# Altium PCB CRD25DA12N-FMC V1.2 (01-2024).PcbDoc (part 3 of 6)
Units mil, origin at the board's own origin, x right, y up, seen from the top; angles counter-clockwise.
Board outline 8000 x 8000 mil, 6 copper layers (Top Layer, Layer 2, Layer 3, Layer 4, Layer 5, Bottom Layer), stack 91 mil thick; 574 components, 325 nets, 1631 pads, 633 vias.
Unrouted connection lines stored in the file: 1.
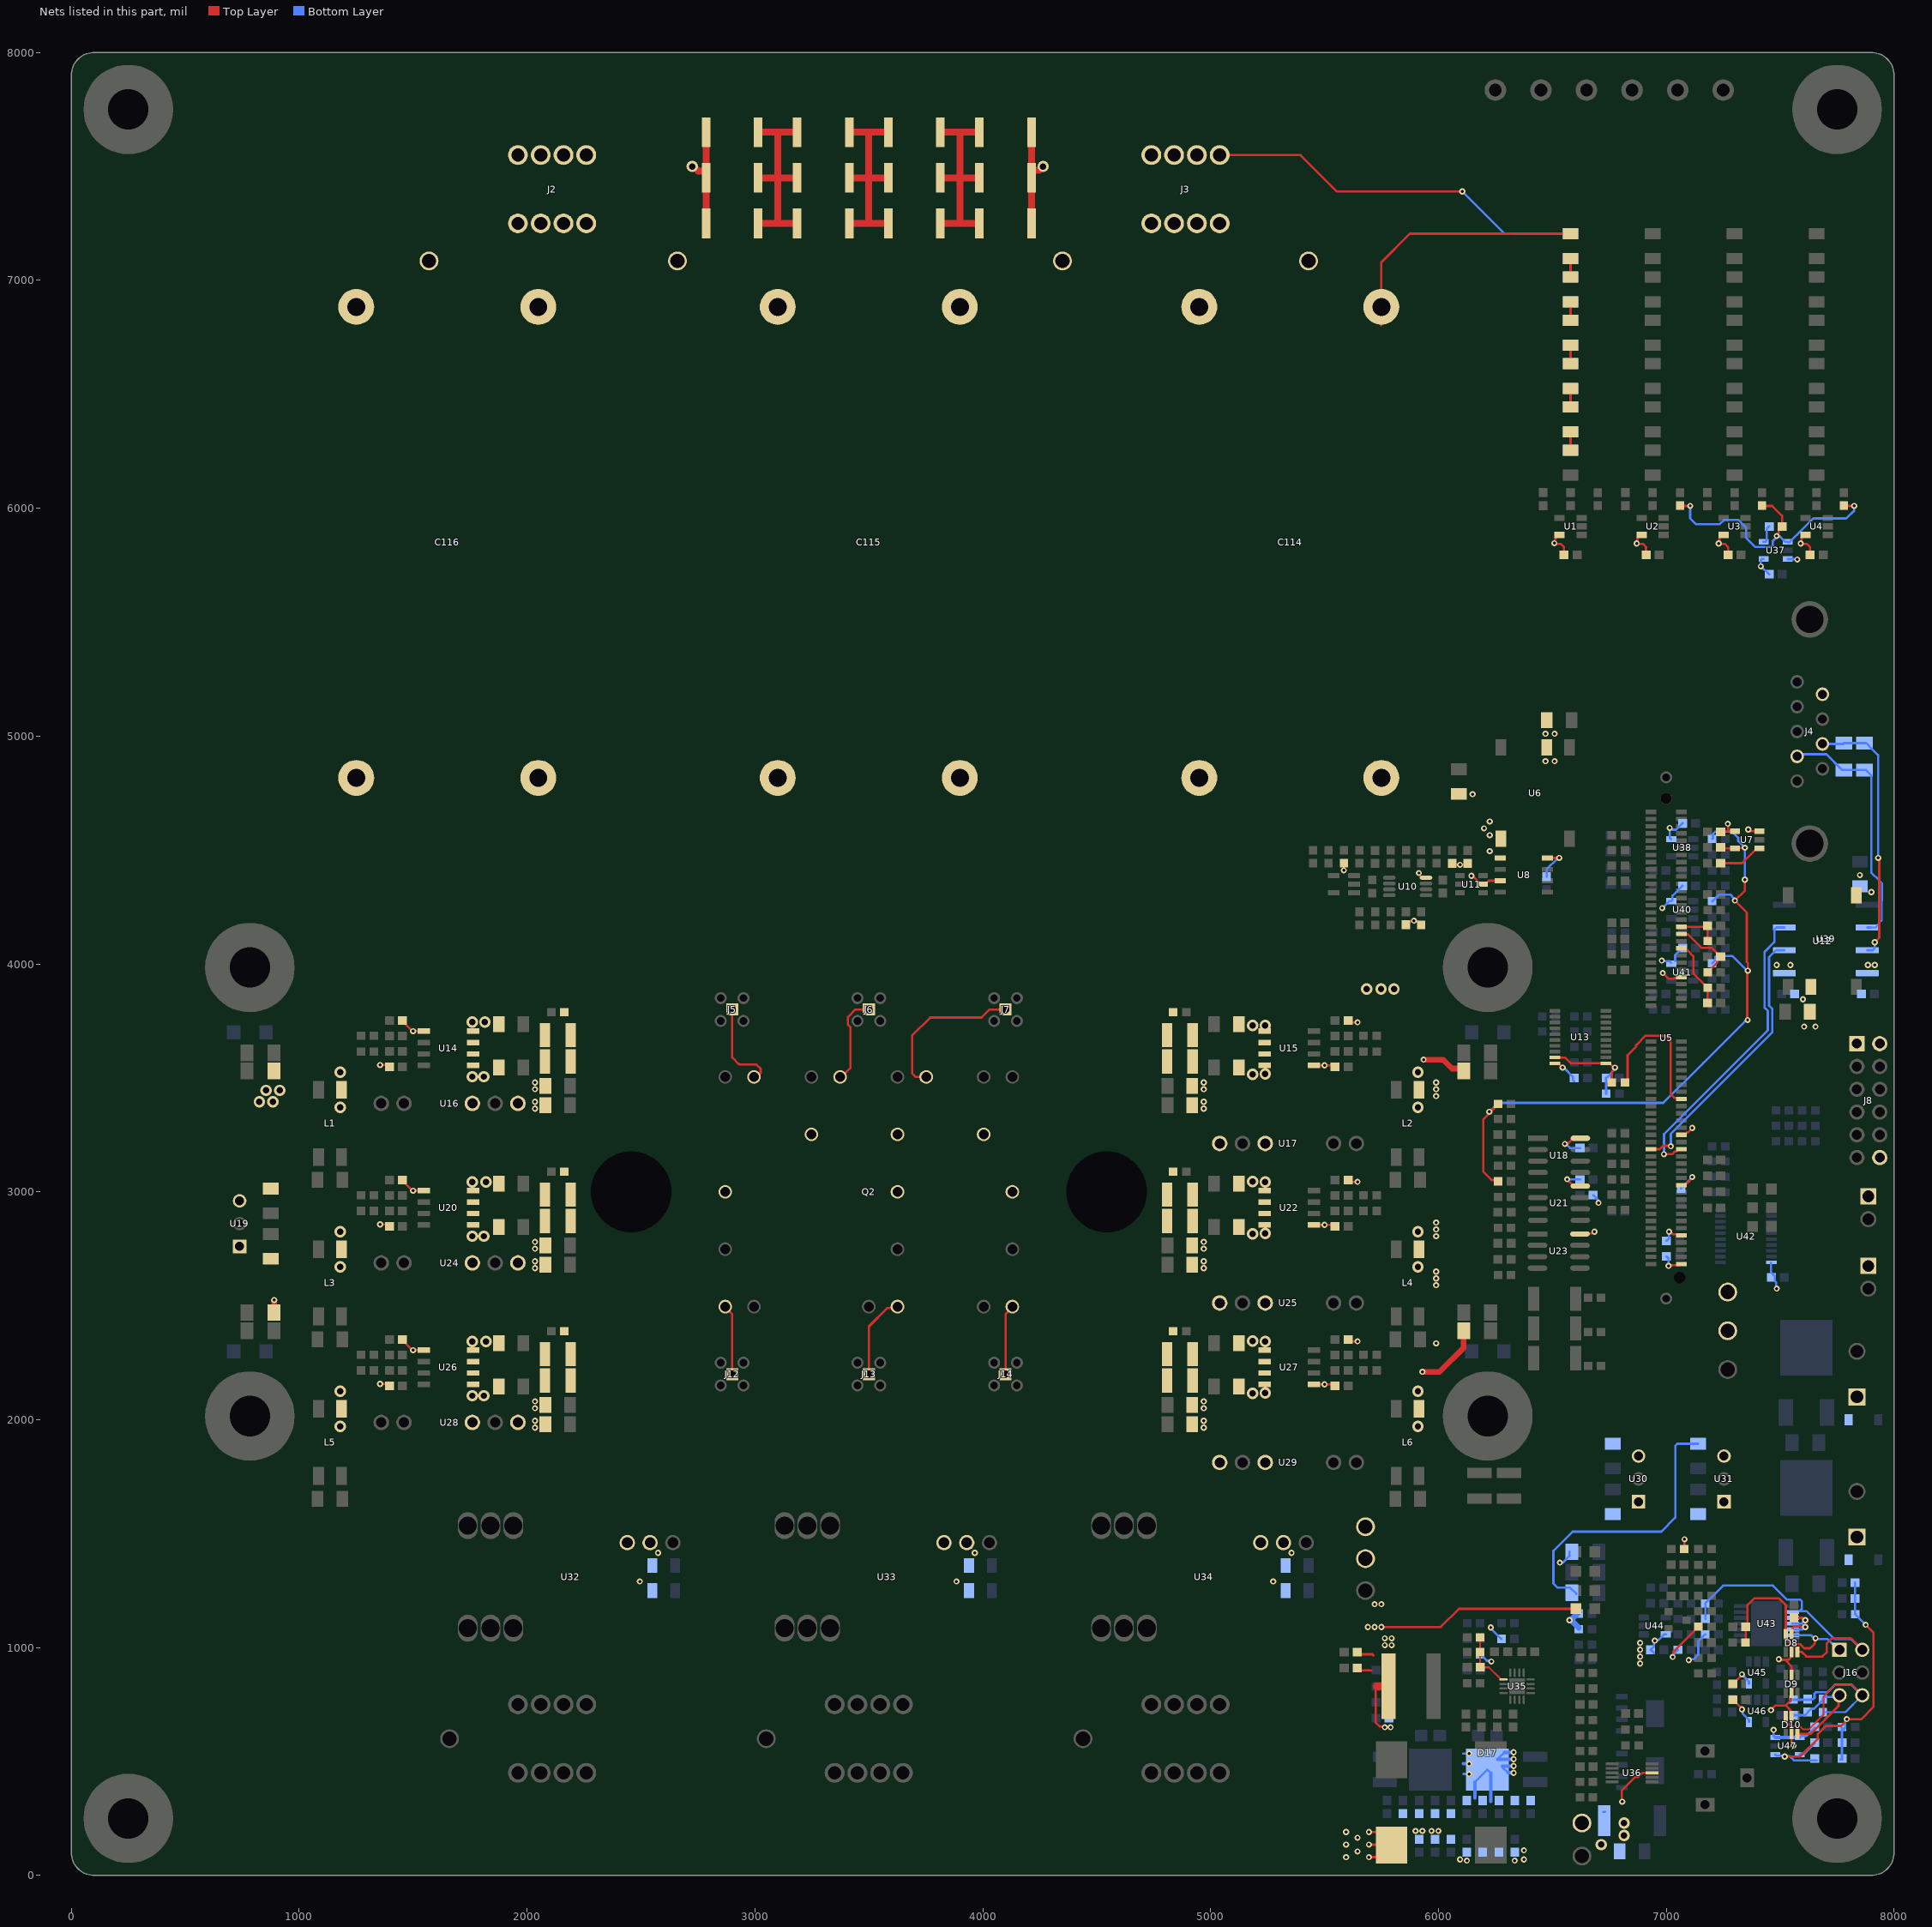
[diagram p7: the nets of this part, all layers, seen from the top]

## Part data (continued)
R51 R223 R227 R231 R234: "RES SMD 4.7K OHM 1% 1/10W 0603", Case Code (Imperial)=0603, Case Code (Metric)=1608, Manufacturer="VISHAY DALE", Max Operating Temperature=155°C, Max Power Dissipation=100mW, Min Operating Temperature=-55°C, Package Quantity=5000, Power Rating=0.1W, Resistance=4.7kΩ, Resistor Type="Thick Film", Supplier Part Number 1=541-3004-6-ND, Temperature Coefficient=100ppm/°C, Tolerance=1%, Voltage Rating=75V
R53: "RES SMD 0 OHM JUMPER 1/10W 0603", Case Code (Imperial)=0603, Case Code (Metric)=1608, Manufacturer="VISHAY DALE", Manufacturer Part Number=CRCW06030000Z0EBC, Max Operating Temperature=155°C, Max Power Dissipation=100mW, Min Operating Temperature=-55°C, Package Quantity=10000, Power Rating=0.1W, Ratings=AEC-Q200, Resistance=0Ω, Resistor Type="Thick Film", Supplier Part Number 1=48P7902, Temperature Coefficient=100ppm/°C, Tolerance=1%, Voltage Rating=75V
R56 R204 R205 R206 R207 R208 R209: "RES 330 OHM 1% 1/10W 0603", Case Code (Imperial)=0603, Case Code (Metric)=1608, Manufacturer=YAGEO, Max Operating Temperature=155°C, Min Operating Temperature=-55°C, Power Rating=0.1W, Resistance=330Ω, Resistor Type="Thick Film", Supplier Part Number 1=4067719, Temperature Coefficient=100ppm/°C, Tolerance=1%, Voltage Rating=50V
R58 R63 R106 R114 R120 R143 R226: "RES SMD 2K OHM 0.5% 1/10W 0603", Case Code (Imperial)=0603, Case Code (Metric)=1608, Manufacturer=YAGEO, Max Operating Temperature=125°C, Max Power Dissipation=100mW, Min Operating Temperature=-55°C, Package Quantity=5000, Power Rating=0.1W, Resistance=2kΩ, Resistor Type="Thin Film", Supplier Part Number 1=6165116, Temperature Coefficient=50ppm/°C, Tolerance=0.5%, Voltage Rating=75V, Voltage Rating (DC)=50V
R60: "RES 249K OHM 1% 1/10W 0603", Case Code (Imperial)=0603, Case Code (Metric)=1608, Manufacturer=STACKPOLE, Max Operating Temperature=155°C, Max Power Dissipation=0.1W, Min Operating Temperature=-55°C, Resistance=249kΩ, Resistor Type="Thick Film", Temperature Coefficient=100ppm/°C, Tolerance=1%
R62: "RES SMD 97.6K OHM 1% 1/10W 0603", Case Code (Imperial)=0603, Case Code (Metric)=1608, Manufacturer=PANASONIC, Max Operating Temperature=155°C, Max Power Dissipation=0.1W, Min Operating Temperature=-55°C, Package Quantity=1, Power Rating=100mW, Resistance=97.6kΩ, Resistance Tolerance=1%, Resistor Type="Thick Film", Supplier Part Number 1=27AC5274, Temperature Coefficient=100ppm/°C, Voltage Rating=75V, Voltage Rating (DC)=50V
R65 R66 R210 R211 R212 R213: "RES SMD 0 OHM JUMPER 1/10W 0603", Case Code (Imperial)=0603, Case Code (Metric)=1608, Manufacturer="VISHAY DALE", Manufacturer Part Number=CRCW06030000Z0EBC, Max Operating Temperature=155°C, Max Power Dissipation=100mW, Min Operating Temperature=-55°C, Package Quantity=10000, Ratings=AEC-Q200, Resistance=0Ω, Resistor Type="Thick Film", Supplier Part Number 1=48P7902, Temperature Coefficient=100ppm/°C, Tolerance=1%, Voltage Rating=75V
R69 R78 R92 R102 R115 R124 R125 R126: "RES SMD 0 OHM JUMPER 3/4W 1210", Case Code (Imperial)=1210, Case Code (Metric)=3225, Manufacturer="VISHAY DALE", Max Operating Temperature=155°C, Max Power Dissipation=750mW, Min Operating Temperature=-55°C, Package Quantity=10, Power Rating=0.75W, Resistance=0Ω, Supplier Part Number 1=71-CRCW12100000Z0EAH
R70 R77 R93 R101 R116 R123: library part CMP-2005-02198-1, "RES 0.91 OHM 1% 1W 1210", Manufacturer="VISHAY DALE", Package=1210, Power=1W
R73 R74 R79 R80 R107 R108 R110 R111 R181 R182 R214 R215 R216 R217 R219: "RES 249 OHM 1% 1/4W 1206", Case Code (Imperial)=1206, Case Code (Metric)=3216, Manufacturer=YAGEO, Max Operating Temperature=155°C, Max Power Dissipation=250mW, Min Operating Temperature=-55°C, Power Rating=0.25W, Resistance=249Ω, Resistor Type="Thick Film", Supplier Part Number 1=1142064, Temperature Coefficient=100ppm/°C, Tolerance=1%, Voltage Rating=200V
R105 R109 R117: library part CMP-1017-00397-1, "RES 100 OHM 1% 3/4W 2010", Case-Metric=5025, Manufacturer=YAGEO, Package=2010, Power="0.75 W", Tolerance="1 %"
R129 R138 R142 R144 R146 R197 R198 R199 R200 R201 R202 R246: "RES 100K OHM 1% 1/10W 0603", Case Code (Imperial)=0603, Case Code (Metric)=1608, Manufacturer=YAGEO, Max Operating Temperature=155°C, Max Power Dissipation=100mW, Min Operating Temperature=-55°C, Power Rating=0.1W, Resistance=100kΩ, Resistance Tolerance=1%, Resistor Type="Thick Film", Supplier Part Number 1=3697448, Temperature Coefficient=100ppm/°C, Voltage Rating=50V, Working Voltage=75V
R132: "RES 20 OHM 5% 1/10W 0603", Case Code (Imperial)=0603, Case Code (Metric)=1608, Manufacturer=YAGEO, Max Operating Temperature=155°C, Max Power Dissipation=100mW, Min Operating Temperature=-55°C, Package Quantity=1, Power Rating=0.1W, Resistance=20Ω, Resistance Tolerance=5%, Resistor Type="Thick Film", Supplier Part Number 1=4144481, Temperature Coefficient=100ppm/°C, Voltage Rating=75V, Voltage Rating (DC)=50V
R134: "RES 5.49K OHM 1% 1/10W 0603", Case Code (Imperial)=0603, Case Code (Metric)=1608, Manufacturer=YAGEO, Max Operating Temperature=155°C, Max Power Dissipation=100mW, Min Operating Temperature=-55°C, Package Quantity=5000, Power Rating=0.1W, Resistance=5.49kΩ, Supplier Part Number 1=1172345, Temperature Coefficient=100ppm/°C, Tolerance=1%, Voltage Rating=50V
R135 R220: "RES 470K OHM 1% 1/10W 0603", Case Code (Imperial)=0603, Case Code (Metric)=1608, Manufacturer=YAGEO, Max Operating Temperature=155°C, Max Power Dissipation=100mW, Min Operating Temperature=-55°C, Package Quantity=1, Power Rating=0.1W, Resistance=470kΩ, Resistance Tolerance=1%, Resistor Type="Thick Film", Supplier Part Number 1=4599155, Temperature Coefficient=100ppm/°C, Voltage Rating=50V
R136: "RES SMD 71.5KOHM 0.5% 1/10W 0603", Case Code (Imperial)=0603, Case Code (Metric)=1608, Manufacturer=YAGEO, Max Operating Temperature=155°C, Max Power Dissipation=0.1W, Min Operating Temperature=-55°C, Package Quantity=5000, Resistance=71.5kΩ, Supplier Part Number 1=3077636, Temperature Coefficient=50ppm/°C, Tolerance=0.5%, Voltage Rating (DC)=50V
R137: "RES SMD 49.9K OHM 1% 1/10W 0603", Case Code (Imperial)=0603, Case Code (Metric)=1608, Manufacturer=YAGEO, Max Operating Temperature=125°C, Max Power Dissipation=100mW, Min Operating Temperature=-55°C, Power Rating=0.1W, Resistance=49.9kΩ, Supplier Part Number 1=3100550, Temperature Coefficient=50ppm/°C, Tolerance=1%, Voltage Rating=75V, Voltage Rating (DC)=50V
R139: "RES 24.9K OHM 1% 1/10W 0603", Case Code (Imperial)=0603, Case Code (Metric)=1608, Manufacturer=YAGEO, Max Operating Temperature=155°C, Max Power Dissipation=100mW, Min Operating Temperature=-55°C, Package Quantity=1, Power Rating=0.1W, Resistance=24.9kΩ, Supplier Part Number 1=3435880, Temperature Coefficient=100ppm/°C, Tolerance=1%, Voltage Rating=50V
R141: "RES 61.9K OHM 1% 1/10W 0603", Case Code (Imperial)=0603, Case Code (Metric)=1608, Manufacturer=YAGEO, Max Operating Temperature=155°C, Max Power Dissipation=100mW, Min Operating Temperature=-55°C, Package Quantity=5000, Power Rating=0.1W, Resistance=61.9kΩ, Supplier Part Number 1=9857970, Temperature Coefficient=100ppm/°C, Tolerance=1%, Voltage Rating=50V, Working Voltage=75V
R147 R148: "RES 2.7M OHM 5% 1/10W 0603", Case Code (Imperial)=0603, Case Code (Metric)=1608, Manufacturer=YAGEO, Max Operating Temperature=155°C, Max Power Dissipation=100mW, Min Operating Temperature=-55°C, Package Quantity=1, Power Rating=0.1W, Resistance=2.7MΩ, Resistor Type="Thick Film", Temperature Coefficient=100ppm/°C, Tolerance=5%, Voltage Rating=75V, Voltage Rating (DC)=50V
R183 R187 R193: "RES 1.33K OHM 1% 1/10W 0603", Case Code (Imperial)=0603, Case Code (Metric)=1608, Manufacturer=STACKPOLE, Max Operating Temperature=155°C, Max Power Dissipation=100mW, Min Operating Temperature=-55°C, Power Rating=0.1W, Resistance=1.33kΩ, Resistor Type="Thick Film", Temperature Coefficient=100ppm/°C, Tolerance=1%
R184 R188 R194: "RES 7.15K OHM 1% 1/10W 0603", Case Code (Imperial)=0603, Case Code (Metric)=1608, Manufacturer=STACKPOLE, Max Operating Temperature=155°C, Max Power Dissipation=100mW, Min Operating Temperature=-55°C, Power Rating=0.1W, Resistance=7.15kΩ, Resistor Type="Thick Film", Temperature Coefficient=100ppm/°C, Tolerance=1%
R185 R190 R195: "RES SMD 4.02KOHM 0.1% 1/10W 0603", Case Code (Imperial)=0603, Case Code (Metric)=1608, Manufacturer=PANASONIC, Manufacturer Part Number=ERA-3AEB4021V, Max Operating Temperature=155°C, Max Power Dissipation=100mW, Min Operating Temperature=-55°C, Package Quantity=1, Power Rating=0.1W, Resistance=4.02kΩ, Resistance Tolerance=0.1%, Resistor Type="Thin Film", Supplier Part Number 1=7087616, Temperature Coefficient=25ppm/°C, Voltage Rating=75V
R186 R191 R196: "RES 7.87K OHM 1% 1/10W 0603", Case Code (Imperial)=0603, Case Code (Metric)=1608, Manufacturer=YAGEO, Max Operating Temperature=155°C, Max Power Dissipation=0.1W, Min Operating Temperature=-55°C, Package Quantity=1, Power Rating=100mW, Resistance=7.87kΩ, Resistor Type="Thick Film", Supplier Part Number 1=49AK2736, Temperature Coefficient=100ppm/°C, Tolerance=1%, Voltage Rating=50V
R218 R224: "RES SMD 3.9K OHM 1% 1/10W 0603", Case Code (Imperial)=0603, Case Code (Metric)=1608, Manufacturer=PANASONIC, Manufacturer Part Number=ERJ-3EKF3901V, Max Operating Temperature=155°C, Max Power Dissipation=100mW, Min Operating Temperature=-55°C, Package Quantity=1, Power Rating=0.1W, Resistance=3.9kΩ, Resistance Tolerance=1%, Resistor Type="Thick Film", Supplier Part Number 1=1229307, Temperature Coefficient=100ppm/°C, Voltage Rating=75V
R221 R228: "RES SMD 15K OHM 0.5% 1/10W 0603", Case Code (Imperial)=0603, Case Code (Metric)=1608, Manufacturer=PANASONIC, Max Operating Temperature=155°C, Max Power Dissipation=100mW, Min Operating Temperature=-55°C, Package Quantity=5000, Power Rating=0.1W, Ratings=AEC-Q200, Resistance=15kΩ, Resistance Tolerance=0.5%, Resistor Type="Thin Film", Supplier Part Number 1=P15KBLCT-ND, Temperature Coefficient=25ppm/°C, Voltage Rating=75V
R225: "RES SMD 34.8KOHM 0.5% 1/10W 0603", Case Code (Imperial)=0603, Case Code (Metric)=1608, Manufacturer=YAGEO, Max Operating Temperature=155°C, Max Power Dissipation=100mW, Min Operating Temperature=-55°C, Package Quantity=5000, Power Rating=0.1W, Resistance=34.8kΩ, Supplier Part Number 1=311-2545-1-ND, Temperature Coefficient=50ppm/°C, Tolerance=0.5%, Voltage Rating=75V, Voltage Rating (DC)=50V
R230: "RES SMD 22.6KOHM 0.5% 1/10W 0603", Case Code (Imperial)=0603, Case Code (Metric)=1608, Manufacturer=YAGEO, Max Operating Temperature=155°C, Max Power Dissipation=0.1W, Min Operating Temperature=-55°C, Package Quantity=5000, Resistance=22.6kΩ, Supplier Part Number 1=311-2487-1-ND, Temperature Coefficient=50ppm/°C, Tolerance=0.5%, Voltage Rating (DC)=50V
R233: "RES SMD 5.36KOHM 0.1% 1/10W 0603", Case Code (Imperial)=0603, Case Code (Metric)=1608, Manufacturer=YAGEO, Max Operating Temperature=155°C, Max Power Dissipation=100mW, Min Operating Temperature=-55°C, Package Quantity=5000, Power Rating=0.1W, Resistance=5.36kΩ, Supplier Part Number 1=YAG1697CT-ND, Temperature Coefficient=25ppm/°C, Tolerance=0.1%, Voltage Rating=75V, Voltage Rating (DC)=50V
R235 R238 R240 R242: "RES SMD 12.1K OHM 0.1% 1/5W 0603", Case Code (Imperial)=0603, Case Code (Metric)=1608, Manufacturer=PANASONIC, Max Operating Temperature=155°C, Max Power Dissipation=0.2W, Min Operating Temperature=-55°C, Resistance=12.1kΩ, Resistor Type="Thick Film", Supplier Part Number 1=68AC5970, Temperature Coefficient=50ppm/°C, Tolerance=0.1%
R236 R239: "RES 47K OHM 1% 1/10W 0603", Case Code (Imperial)=0603, Case Code (Metric)=1608, Manufacturer=YAGEO, Max Operating Temperature=155°C, Max Power Dissipation=100mW, Min Operating Temperature=-55°C, Package Quantity=1, Power Rating=0.1W, Resistance=47kΩ, Resistance Tolerance=1%, Resistor Type="Thick Film", Supplier Part Number 1=6616189, Temperature Coefficient=100ppm/°C, Voltage Rating=50V
R244 R245: "RES SMD 10 OHM 1% 3/4W 1210", Case Code (Imperial)=1210, Case Code (Metric)=3225, Manufacturer=VISHAY, Max Operating Temperature=155°C, Max Power Dissipation=750mW, Min Operating Temperature=-55°C, Package Quantity=10, Power Rating=0.75W, Ratings=AEC-Q200, Resistance=10Ω, Supplier Part Number 1=71-CRCW121010R0FKEAH, Temperature Coefficient=100ppm/°C, Tolerance=1%, Voltage Rating=200V
R247: "RES 0.01 OHM 1% 2W 2512", Case Code (Imperial)=2512, Case Code (Metric)=6432, Manufacturer=YAGEO, Max Operating Temperature=170°C, Max Power Dissipation=2W, Min Operating Temperature=-55°C, Resistance=10mΩ, Resistor Type="Metal Film", Supplier Part Number 1=1995902P, Temperature Coefficient=50ppm/°C, Tolerance=1%
TP1 TP2 TP5 TP6 TP8 TP9 TP14: library part CMP-1672-00002-4, "PC TEST POINT MULTIPURPOSE RED", Colour=Red, Manufacturer=KEYSTONE, Package=N/A, Package Quantity=100
TP3 TP4 TP7 TP10 TP15: library part CMP-1672-00003-4, "PC TEST POINT MULTIPURPOSE BLACK", Colour=Black, Manufacturer=KEYSTONE, Package=N/A, Package Quantity=100
TP11 TP12 TP13: library part CMP-1672-00004-4, "PC TEST POINT MULTIPURPOSE WHITE", Colour=White, Manufacturer=KEYSTONE, Package=N/A, Package Quantity=100
U1 U2 U3 U4 U38 U40 U41 U44 U45 U46: library part CMP-0384-02059-2, "IC OPAMP GP 1 CIRCUIT TSOT23-5", Amplifiers Per Package=1, Generic Part Number=AD8615, Input Bias Current=200fA, Input Offset Voltage=80uV, Manufacturer="ANALOG DEVICES", Package=TSOT-23-5
U5: "EVAL BOARD FOR TMS320F280039C", Manufacturer="TEXAS INSTRUMENTS", Package=N/A, Supplier Part Number 1=595-TMDSCNCD280039C
U6 U12: "DC DC CONVERTER 5V 1W", Case/Package=SMD/SMT, Current - Output 1=200mA, Isolation Voltage=2kV, Manufacturer=RECOM, Max Input Voltage=3.63V, Max Operating Temperature=100°C, Max Output Power=1W, Max Output Voltage=5V, Min Input Voltage=2.97V, Min Operating Temperature=-40°C, Package=8-SMD, Supplier Part Number 1=945-R1SE-3.305/H2-RCT-ND
U7 U37 U47: "AUTOMOTIVE LOW-DRIFT, LOW-POWER,", Manufacturer="TEXAS INSTRUMENTS", Package=TSOT-23-5, Supplier Part Number 1=595-REF2033QDDCRQ1
U8: library part CMP-0328-00055-4, "DGTL ISO 2500VRMS 1CH GP 8SOIC", Case/Package=8-SOIC, Insulation Rating(VRMS)=2500, Manufacturer="TEXAS INSTRUMENTS", Rating=Catalog, Supply Voltage(s)(V)="3.3, 5"
U9: "IC VREF SHUNT ADJ 2% SOT23-5", Case/Package=SOT-23-5, Cathode Current=60uA, Manufacturer=STMICROELECTRONICS, Manufacturer Print=ST, Max Input Voltage=10V, Max Operating Temperature=125°C, Max Output Current=30mA, Max Output Voltage=6V, Min Operating Temperature=-40°C, Min Output Voltage=1.24V, Package Quantity=1, Temperature Coefficient=100ppm/°C, Tolerance=2%
U10: "IC OPAMP GP 2 CIRCUIT 8MSOP", Case/Package=MSOP, Input Bias Current=1pA, Input Offset Voltage (Vos)=3mV, Input Offset Voltage-Max=5mV, Manufacturer=MICROCHIP, Max Operating Temperature=125°C, Max Supply Voltage=5.5V, Min Operating Temperature=-40°C, Min Supply Voltage=2.4V, Nominal Supply Current=1mA, Output Current=25mA, Package=8-MSOP, Package Quantity=100, Power Supply Rejection Ratio (PSRR)=70dB, Supplier Part Number 1=20T6022, Voltage Gain=110dB
U11: "IC OSC SILICON PROG TSOT23-6", Frequency=3.81Hz, Manufacturer="ANALOG DEVICES", Max Operating Temperature=70°C, Max Supply Voltage=5.5V, Min Operating Temperature=0°C, Min Supply Voltage=2.25V, Operating Supply Current=365uA, Package=TSOT-23-6, Package Quantity=1, Supplier Part Number 1=505-LTC6992CS6-2#TRMPBFDKR-ND
U13 U42: library part CMP-0440-01163-3, "IC BUF NON-INVERT 5.5V 20TSSOP", F @ Nom Voltage(Max)(Mhz)=110, Generic Part Number=SN74LV541AT, ICC @ Nom Voltage(Max)(mA)=0.02, Manufacturer="TEXAS INSTRUMENTS", Operating Temperature Range(C)="-40 to 125", Package=20-TSSOP, Rating=Catalog, tpd @ Nom Voltage(Max)(ns)=7.9, Voltage(Nom)(V)=5
U14 U15 U20 U22 U26 U27: "5A/5A, 3-KVRMS SINGLE-CHANNEL IS", Manufacturer="TEXAS INSTRUMENTS", Max Operating Temperature=125°C, Mfr_Name="Texas Instruments", Min Operating Temperature=-40°C, Package=8-SOIC, Supplier Part Number 1=296-47508-ND, Working Voltage=990V
U16 U17 U24 U25 U28 U29: "DC DC CONVERTER 15V -3V 1.7W", Manufacturer=MURATA, Package=7-SIP, Supplier Part Number 1=580-MGJ2D121503SC
U18 U21 U23: library part CMP-04896-000023-1, "IC COMPARATOR R-R HI-SPD 8-SOIC", Ambient Temperature Range High=+125°C, Ambient Temperature Range Low=-40°C, Input Bias Current=0.000002uA, Input Offset Voltage=1mV, Manufacturer="TEXAS INSTRUMENTS", Max Junction Temp=+150°C, Max Supply Voltage=5.5V, Min Supply Voltage=2.2V, Nominal Supply Current=3.2mA, Package=8-SOIC, Temperature="-40°C to +125°C"
U19 U31: "DC DC CONVERTER 5V 5W", Case/Package=SIP, Current - Output 1=1A, Manufacturer=RECOM, Max Input Voltage=28V, Max Operating Temperature=85°C, Max Output Voltage=5V, Max Power Dissipation=5W, Min Input Voltage=8V, Min Operating Temperature=-40°C, Package=3-SIP, Package Quantity=42, Supplier Part Number 1=1446013
U30: "DC DC CONVERTER 3.3V 3W", Case/Package=SIP, Manufacturer=RECOM, Max Input Voltage=28V, Max Operating Temperature=85°C, Max Output Current=1A, Max Output Power=3.3W, Max Output Voltage=3.3V, Max Power Dissipation=3W, Min Input Voltage=8V, Min Input Voltage (DC)=7V, Min Operating Temperature=-40°C, Package=3-SIP, Supplier Part Number 1=9176626
U32 U33 U34: "SENSOR CURRENT HALL 50A AC/DC", Case/Package=Module, Current Rating=50A, Frequency=200kHz, Manufacturer=LEM, Max Operating Temperature=85°C, Max Supply Current=35mA, Min Operating Temperature=-25°C, Operating Supply Voltage=15V, Package=N/A, Package Quantity=12, Secondary Current=25mA, Supplier Part Number 1=44W8442
U35: "IC REG MULT CONFG ADJ 6.5A 16QFN", Case/Package=16-WFQFN, Manufacturer="TEXAS INSTRUMENTS", Supplier Part Number 1=595-LM5157QRTERQ1
U36: "IC SURGE SUPPRESSION ADJ 10MSOP", Manufacturer="ANALOG DEVICES", Package=10-MSOP, Supplier Part Number 1=505-LTC4368IMS-2#PBF-ND
U39: "IC TXRX/ISO HALF 1/1 8SOP", Drivers Per Package=1, Manufacturer="TEXAS INSTRUMENTS", Package=8-SOP, Rating=Catalog
U43: library part CMP-04895-000282-1, "IC POWER 2 CIRCUIT 14HTSSOP", Manufacturer="TEXAS INSTRUMENTS", Package=14-PowerTSSOP

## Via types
v1: diameter 27, hole 13, Top Layer to Bottom Layer, tented both sides, 537 vias
v2: diameter 50, hole 28, Top Layer to Bottom Layer, tented both sides, 76 vias
v3: diameter 19.68, hole 7.87, Top Layer to Bottom Layer, tented top, 15 vias
v4: diameter 19.68, hole 7.87, Top Layer to Bottom Layer, tented both sides, 5 vias

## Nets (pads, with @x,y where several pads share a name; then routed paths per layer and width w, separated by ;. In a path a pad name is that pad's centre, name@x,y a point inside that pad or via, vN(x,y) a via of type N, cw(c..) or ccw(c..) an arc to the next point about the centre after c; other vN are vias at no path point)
+1.65V_I: C17.1 U7.1 | length 196.7
  Top Layer w10: C17.1@7238.58,4442 7332.71,4442 7398.31,4507.6 U7.1@7408.15,4507.6
+1.65V_R: C165.1 C169.1 C185.1 C187.1 C188.1 R222.1 R243.1 U47.1 | length 1476.3
  Top Layer w10: v1(7520,521.49) 7586.8,521.49 7665,599.69 7665,620.31 7700.64,655.94 7767.72,655.94 7775.01,663.23 7775.01,663.81 7792.41,681.2 v1(7792.41,685.8) 7793.21,685 7820.91,685 7855,685 7910,740 7910,1065 v1(7875,1100)
  Bottom Layer w10: U47.1@7478.7,530.2 7484.15,524.74 7516.75,524.74 v1(7520,521.49) 7521.6,523.09 7541.91,523.09 7560,505 C188.1@7660.37,505 ; C187.1@7765.47,508 7771.42,508 C187.1@7771.42,513 7771.42,577.05 7770.47,578 7771.42,578 C185.1@7771.42,583 7771.42,634 ; R243.1@7771.38,647 7771.42,646.96 7771.42,634 ; v1(7792.41,685.8) 7792.41,681.2 7785.24,674.03 7785.24,646.96 7772.28,634 7771.42,634 ; C165.1@7828.58,1285 C169.1@7828.58,1215 C169.1@7828.58,1215 R222.1@7828.62,1146 7829.53,1146 7875,1100.53 v1(7875,1100)
+1.65V_V: C5.1 R40.2 R42.2 R44.2 U37.1 | length 1288.1
  Top Layer w10: R40.2@7060,6011.38 7061.38,6010 v1(7105,6010) ; R42.2@7420,6011.38 7421.38,6010 7465,6010 7508.58,5966.42 C5.1@7508.58,5920 7507.63,5920 7493.76,5906.14 7493.76,5891.72 7484.64,5882.6 v1(7484.64,5878) ; R44.2@7780,6011.38 7781.38,6010 v1(7825,6010)
  Bottom Layer w10: v1(7105,6010) 7105,5955 7130,5930 7234.54,5930 7253.04,5948.5 7316.81,5948.5 7350.91,5914.39 7350.91,5869.09 7390.41,5829.59 7459.9,5829.59 7467.25,5836.94 7467.25,5856.01 7484.64,5873.4 v1(7484.64,5878) 7487.9,5874.75 7500.96,5874.75 7523.31,5852.4 U37.1@7533.15,5852.4 ; U37.1@7533.15,5851.2 7541.79,5851.2 7574.09,5883.5 7645.59,5955 7790,5955 7825,5990 v1(7825,6010)
+3.3V: C6.1 C7.1 C8.1 C9.1 C10.1 C27.1 C104.1 C106.1 C123.1 C131.1 C133.1 C137.1 C139.1 C147.1 C150.1 C153.1 C159.1 C174.1 J8.1 R127.2 R215.1 R228.2 TP5.1 U1.5 U2.5 U3.5 U4.5 U6.2 U8.8 U12.2 U18.8 U21.8 U23.8 U30.3 U38.5 U39.1 U40.5 U41.5 U44.5 U45.5 U46.5 | length 2122.7
  Top Layer w10: U8.8@6478.35,4465 v1@6525,4465 ; U1.5@6531.77,5882.6 6522.91,5882.6 6514.13,5873.82 6514.13,5864.96 6511.83,5862.66 6511.83,5849.68 v1(6508.58,5846.42) 6511.14,5843.86 6537.56,5843.86 6551.42,5830 C6.1@6551.42,5795 ; v1(6555,3210) 6558.25,3213.25 6570.07,3213.25 6591.81,3235 U18.8@6623.06,3235 ; v1(6565,3055) 6565,3053.41 6593.41,3025 U21.8@6623.06,3025 U21.8@6651.78,3025 ; U23.8@6621.11,2815 6655.85,2815 6658.32,2817.47 6672.87,2817.47 6680.4,2825 v1(6685,2825) ; U2.5@6891.77,5882.6 6882.91,5882.6 6874.13,5873.82 6874.13,5864.96 6873.25,5864.08 6873.25,5848.25 v1(6870,5845) 6871.14,5843.86 6897.56,5843.86 6911.42,5830 C7.1@6911.42,5795 ; R127.2@7078.62,1432 7080,1433.38 v1(7080,1475) ; U3.5@7251.77,5882.6 7242.91,5882.6 7234.13,5873.82 7234.13,5864.96 7233.25,5864.08 7233.25,5848.25 v1(7230,5845) 7231.14,5843.86 7257.56,5843.86 7271.42,5830 C8.1@7271.42,5795 ; C106.1@7291.42,771 7292.37,771 7332.36,731.01 v1(7332.36,728.64) ; C104.1@7291.42,840 7292.37,840 7332.36,879.99 v1(7332.36,882.36) ; U4.5@7611.77,5882.6 7602.91,5882.6 7594.13,5873.82 7594.13,5864.96 7593.25,5864.08 7593.25,5848.25 v1(7590,5845) 7591.14,5843.86 7617.56,5843.86 7631.42,5830 C9.1@7631.42,5795
  Bottom Layer w10: C131.1@6475,4383.58 6475,4415 6521.75,4461.75 6522.15,4461.75 6530,4469.6 v1@6530,4470 ; v1(6533.01,1372.78) 6533.48,1373.25 6547.07,1373.25 6575,1401.18 R215.1@6575,1420 ; v1(6555,3210) 6559.31,3210 6577.31,3192 C147.1@6621.42,3192 ; v1(6565,3055) 6620.42,3055 C150.1@6621.42,3054 ; C153.1@6678.58,2985 6679.53,2985 6699.46,2965.06 6699.46,2954.61 v1(6702.72,2951.35) v1@6699.46,2948.1 ; C174.1@6931.42,990 C174.1@6932.37,990 ; C174.1@6946.24,976.14 C174.1@6932.37,990 ; v1(6950,1030) 6950,1025.4 6946.24,1021.64 6946.24,1003.86 C174.1@6932.37,990 ; 6965.02,1033.25 6989.37,1057.6 U44.5@6998.23,1057.6 ; v1(6980.22,4014.95) 6983.47,4011.7 7014.48,4011.7 U41.5@7021.77,4004.4 ; v1(6982.51,4245) 7012.91,4275.4 U40.5@7021.77,4275.4 7027.47,4281.1 7027.47,4300 7070.47,4343 C133.1@7071.42,4343 ; U38.5@7021.77,4547.4 7015.1,4554.07 v1(7015.1,4596.7) 7019.7,4596.7 7027.41,4589 7042.47,4589 7070.47,4617 C123.1@7071.42,4617 ; U41.5@7039.41,4013.18 7039.41,4038.94 7070.47,4070 C137.1@7071.42,4070 ; v1(7099.02,944.96) 7102.27,948.21 7119.21,948.21 7140.61,969.62 7140.61,1028.14 7170.47,1058 R228.2@7171.38,1058 ; v1(7332.36,728.64) 7335.62,725.38 7335.62,709.38 7362.6,682.4 U46.5@7362.6,673.54 ; v1(7332.36,882.36) 7332.36,880.87 7362.6,850.63 U45.5@7362.6,841.77
  other v1: 7605,3725 7655,3725 7600,3845 7485,3995 7545,3995 6530,4465 6470,4890 6510,4890 6470,5010 6510,5010
+3.3V_I: C13.1 R82.2 R91.2 R183.2 R187.2 R193.2 U7.5 | length 3236.5
  Top Layer w10: v1(6223.67,3350.99) 6225.46,3350.99 6270.24,3395.77 6275.24,3395.77 6227.88,3348.41 6196.5,3317.03 6196.5,3088.5 6233.38,3051.62 6255.71,3051.62 R91.2@6261.38,3045.96 ; C13.1@7238.58,4511 7241.98,4507.6 U7.5@7301.85,4507.6 7303.05,4508.8 7343.8,4508.8 v1(7345,4510) ; v1(7345,4370) 7345,4322.29 v1(7300.98,4278.27) 7353.5,4225.75 7353.5,4008.5 7357.89,4004.11 v1(7357.89,3970) ; v1@7355,3970 7355,3756.03 v1(7357.21,3753.81)
  Bottom Layer w10: v1(6223.67,3350.99) 6262.68,3390 6986.9,3390 7162.57,3565.67 7345.25,3748.35 7347.15,3748.35 7352.61,3753.81 v1(7357.21,3753.81) ; R193.2@7201.38,4003 7202.04,4003 7215,4015.96 7215,4029.14 7220.86,4035 7290,4035 7355,3970 v1(7357.89,3970) ; R187.2@7201.38,4275 7202.28,4275 7231.24,4303.96 7282.04,4303.96 7289.11,4296.88 7289.11,4294.74 7300.98,4282.87 v1(7300.98,4278.27) ; R183.2@7201.38,4548 7205,4551.62 7205,4570 7215,4580 7289.69,4580 7315.72,4553.97 7315.72,4539.28 v1(7345,4510) v1(7345,4370)
+3.3V_R: C186.1 U47.5 | length 86.2
  Bottom Layer w10: U47.5@7585,530.2 7591.81,537.01 7609.48,537.01 7650.47,578 C186.1@7651.42,578
+3.3V_V: C121.1 U37.5 | length 82
  Bottom Layer w10: U37.5@7426.85,5852.4 7434.01,5852.4 7440.82,5859.21 7440.82,5909.4 C121.1@7451.42,5920
+5V: C12.1 C29.1 C39.1 C51.1 C65.1 C76.1 C86.1 C122.1 C144.1 C151.1 C155.1 C156.1 C157.1 C158.1 C184.1 J8.2 R219.1 TP6.1 U5.48 U5.84 U5.98 U5.112 U5.120 U7.3 U7.4 U13.20 U15.1 U22.1 U27.1 U31.3 U37.3 U37.4 U42.20 U47.3 U47.4 | length 2969.6
  Top Layer w10: U27.1@5453.27,2155 5544.42,2155 C86.1@5551.42,2148 ; U22.1@5453.27,2855 5544.42,2855 C65.1@5551.42,2848 ; U15.1@5453.27,3555 5544.42,3555 C39.1@5551.42,3548 ; C76.1@5608.58,2352 5617.08,2343.5 v1(5645,2343.5) ; C51.1@5608.58,3052 5617.08,3043.5 v1(5645,3043.5) ; C29.1@5608.58,3752 5617.08,3743.5 v1(5645,3743.5) ; U13.20@6510.59,3563.82 6526.34,3563.82 6536.9,3553.25 6546.75,3553.25 v1@6550,3550 ; v1(6984.55,3959.95) 6985.18,3959.95 7009.51,3935.62 7033.12,3935.62 7035.37,3937.87 7062.09,3937.87 U5.48@7066.93,3942.72 ; v1(7010,2675) 7013.03,2678.03 7062.09,2678.03 U5.120@7066.93,2682.87 ; v1(7012.3,2825) 7016.9,2825 7028.31,2813.59 7062.19,2813.59 U5.112@7066.93,2808.86 ; U5.98@7066.93,3029.33 7080.71,3029.33 7091.36,3039.98 7095.11,3039.98 7103.03,3047.91 7103.03,3049.17 7114.05,3060.19 v1(7114.05,3064.79) ; U5.84@7066.93,3249.8 7080.71,3249.8 7091.36,3260.46 7095.11,3260.46 7114.05,3279.4 v1(7114.05,3280) ; C12.1@7238.58,4580 7240.98,4582.4 7271.41,4582.4 ; v1(7270,4615) 7271.41,4613.59 7271.41,4582.4 ; U7.4@7301.85,4582.4 7271.41,4582.4 ; v1(7360,4590) 7364.6,4590 7372.2,4582.4 U7.3@7408.15,4582.4
  Bottom Layer w10: v1(6545,3545) 6548.25,3541.75 6553.73,3541.75 6590,3505.47 6590,3490 C144.1@6595,3485 ; R219.1@6605.54,1235 6577.04,1263.5 6521.93,1263.5 6504.51,1280.93 6504.51,1424.51 6588.5,1508.5 6978.5,1508.5 7040,1570 7040,1885 7049.19,1894.19 C158.1@7140,1894.19 ; C156.1@7001.42,2716 7010,2707.42 v1(7010,2675) ; C155.1@7001.42,2785 7012.3,2795.88 v1(7012.3,2825) ; C151.1@7065,3015 7065,3015.95 7113.84,3064.79 v1(7114.05,3064.79) ; U37.4@7426.85,5777.6 7421.81,5777.6 7415,5770.79 v1(7415,5745) 7415.47,5745 7450.47,5710 C122.1@7451.42,5710 ; U42.20@7459.41,2688.82 7459.41,2647.05 7476.24,2630.22 7476.24,2608.36 7481.75,2602.85 7481.75,2578.25 v1(7485,2575) ; v1(7471.28,638.72) 7471.28,611.81 7478.09,605 U47.3@7478.7,605 ; U37.3@7533.15,5777.6 7534.45,5776.3 7573.7,5776.3 v1(7575,5775) ; U47.4@7588.19,605 U47.4@7585,605 7591.81,611.81 7615.28,611.81 7650.47,647 C184.1@7651.42,647
  Bottom Layer w15: U47.3@7478.7,605 U47.4@7585,605
  other v1: 5500,2155 5990,2335 5990,2590 5990,2620 5990,2650 5990,2805 5990,2835 5500,2855 5990,2865 5990,3420 5990,3450 5990,3480 5500,3555
+5V_ALT: C28.1 C38.1 C50.1 C54.1 C64.1 C75.1 C85.1 U14.1 U19.3 U20.1 U26.1 | length 475.4
  Top Layer w10: v1(1355,2156.5) 1382.92,2156.5 C85.1@1391.42,2148 ; v1(1355,2856.5) 1382.92,2856.5 C64.1@1391.42,2848 ; v1(1355,3556.5) 1382.92,3556.5 C38.1@1391.42,3548 ; C75.1@1448.58,2352 1449.53,2352 1495,2306.53 1495,2305 U26.1@1546.73,2305 ; C50.1@1448.58,3052 1449.53,3052 1495,3006.53 1495,3005 U20.1@1546.73,3005 ; C28.1@1448.58,3752 1449.53,3752 1495,3706.53 1495,3705 U14.1@1546.73,3705
  other v1: 1500,2305 1500,3005 1500,3705
+5V_ISO: C126.1 C138.1 J4.9 U12.5 U39.8
  other v1: 7885,3995 7915,3995 7900,4315 7850,4390
+5V_NTC: C11.1 C15.1 C16.1 C20.1 R48.2 R62.2 U6.5 U8.1 U8.3 U10.8 U11.5 | length 357.5
  Top Layer w10: v1(5585,4410.71) 5585,4435.38 R48.2@5586,4436.38 ; C20.1@5858,4171.42 5858,4172.37 5871.86,4186.24 5884.29,4186.24 5888.01,4189.96 v1(5892.61,4189.96) 5897.21,4189.96 5901.93,4185.24 5912.04,4185.24 5925,4172.28 R62.2@5925,4171.38 ; v1(5914.2,4399.02) 5917.45,4395.76 5917.45,4390.03 5929.1,4378.39 U10.8@5945.71,4378.39 ; C15.1@6060,4436.42 6061.42,4435 v1(6095,4435) 6126.58,4435 C16.1@6128,4436.42 ; v1(6145,4387) 6149.34,4387 6186.34,4350 U11.5@6190,4350 ; U11.5@6196.18,4350 6206.02,4350 6221.02,4365 U8.3@6265,4365
  other v1: 6225,4495 6225,4565 6200,4595 6225,4625 6150,4745
+12V: C66.1 C99.1 C102.1 C160.1 C161.1 C176.1 C179.1 C182.1 C183.1 C207.1 D15.1 D16.1 J8.12 J9.1 J10.1 J11.1 J15.1 L1.1 L2.1 L3.1 L4.1 L5.1 L6.1 L7.1 R79.1 R80.1 R107.1 R111.1 R225.2 R247.2 TP14.1 U19.1 U30.1 U31.1 U36.8 | length 1233.7
  Top Layer w10: C102.1@5643.58,900 5705,900 ; C99.1@5643.58,970 5710,970 5715,965 ; 5730.86,830 5725,824.14 5725,670 5741.75,653.25 5758.25,653.25 v1@5760,655 ; v1(6806.5,323.5) 6805,325 6805,373.06 6863.39,431.45 6876.45,431.45 6894.84,449.84 U36.8@6935.16,449.84
  Top Layer w25: R107.1@889.1,2470 885.21,2473.9 890,2478.69 v1(890,2525) ; v1(5930,2210) 6005,2210 6110.9,2315.9 R111.1@6110.9,2390 ; v1(5935,3580) 6020,3580 6059.38,3540.62 6100.28,3540.62 R80.1@6110.9,3530
  Top Layer w35: 5730.86,830 L7.1@5781.57,830
  Bottom Layer w10: v1(6230,1088) 6230,1083.47 6275.47,1038 R225.2@6276.38,1038 ; R247.2@6724.07,278.08 R247.2@6731.14,278.08
  other v1: 5765,650 5790,650 5765,1010 5795,1010 5765,1040 5795,1040
  other v2: 6715,135 6815,175 6815,230 1180,1970 5910,1970 1180,2125 5910,2125 1180,2670 5910,2670 1180,2825 5910,2825 1180,3370 5910,3370 825,3395 885,3395 855,3445 915,3445 1180,3525 5910,3525 5685,3890 5748.12,3890 5805,3890
+15V: C96.1 C162.1 C163.1 C164.1 C189.2 C190.1 C191.1 C192.1 C193.1 C199.1 C200.1 C201.1 C202.1 D8.2 D8.5 D9.2 D9.5 D10.2 D10.5 D17.1 R133.2 R223.2 R227.2 R232.2 R233.2 TP8.1 U32.8 U33.8 U34.8 U43.10 U43.11 U43.12 | length 1792.9
  Top Layer w10: v1(7028.2,958.5) 7031.16,961.46 7031.16,981.69 7140.47,1091 R133.2@7141.38,1091 ; v1(7459.43,725.36) 7479.79,745.72 7525.11,745.72 ; v1(7494.07,948.46) 7496.54,945.99 7520,945.99 ; D10.2@7550,620.63 7550,582.22 7558,574.22 v1(7558,569.62) ; D10.5@7550,699.37 7546.14,703.23 7546.14,724.69 7525.11,745.72 ; D9.2@7550,800.63 7546.14,796.77 7546.14,766.75 7525.11,745.72 ; D9.5@7550,879.37 7549.98,917.01 7520,946.99 7537.82,946.99 7546.14,955.31 7546.14,976.77 D8.2@7550,980.63 ; D8.5@7550,1059.37 7553.86,1063.23 7553.86,1084.69 7562.18,1093.01 7589.01,1093.01 7590.51,1091.5 7608.5,1091.5 v1(7610,1090) ; C96.1@7560,1131.42 7593.98,1131.42 7605.4,1120 v1(7610,1120)
  Bottom Layer w10: 6108.5,535 v1(6135,535) ; 6110,445 v1(6135,445) ; D17.1@6160,409.06 D17.1@6215,464.06 D17.1@6230,449.06 ; R233.2@6183.62,970 6184.53,970 6212.64,941.89 6228.7,941.89 v1(6231.95,938.64) ; D17.1@6260,510 6259.69,510.31 D17.1@6289.37,540 ; D17.1@6280.47,480 6280.47,474.02 D17.1@6304.49,450 ; v1@6583.73,1123.25 6578.25,1123.25 v1(6575,1120) 6578.25,1116.75 v1@6585.73,1116.75 ; R227.2@6615.47,1087 R227.2@6616.38,1087 ; R223.2@6615.47,1155 R223.2@6616.38,1155 ; v1(7028.2,958.5) 7031.16,961.46 7031.16,970.69 7050.47,990 R232.2@7051.38,990 ; U43.12@7554.17,1079.41 7597.69,1079.41 7608.28,1090 v1(7610,1090) 7595,1105 ; U43.11@7554.17,1105 7595,1105 ; U43.10@7555.91,1128.86 U43.10@7554.17,1130.59 7596.29,1130.59 7606.88,1120 v1(7610,1120) 7595,1105
  Bottom Layer w15: 6110,490 v1(6135,490) ; 6160,340 D17.1@6160,409.06 ; 6230,325 D17.1@6230,449.06 ; D17.1@6260,510 v1(6330,510) ; D17.1@6280.47,480 v1(6330,480) ; D17.1@6289.37,540 v1(6330,540) ; D17.1@6304.49,450 v1(6330,450)
  Bottom Layer w25: v1@6583.73,1123.25 R223.2@6615.47,1155 ; v1@6585.73,1116.75 R227.2@6615.47,1087
  other v1: 6125,65 6335,65 6095,70 6375,70 6375,110 6885,930 6885,960 6885,990 6885,1020 2575,1415 3965,1415 5355,1415
+15V_U_HS: C62.1 C71.1 U20.5 U24.7
  other v1: 2035,2665 2035,2695
  other v2: 1760,2805 1810,2805
+15V_U_LS: C83.1 C89.1 U26.5 U28.7
  other v1: 2035,1965 2035,1995
  other v2: 1760,2105 1810,2105
+15V_V_HS: C36.1 C42.1 U14.5 U16.7
  other v1: 2035,3365 2035,3395
  other v2: 1760,3505 1810,3505
+15V_V_LS: C78.1 C90.1 U27.5 U29.7
  other v1: 4970,1965 4970,1995
  other v2: 5240,2342.8 5185,2345
+15V_W_HS: C31.1 C43.1 U15.5 U17.7
  other v1: 4970,3365 4970,3395
  other v2: 5185,3730 5240,3730
+15V_W_LS: C53.1 C72.1 U22.5 U25.7
  other v1: 4970,2665 4970,2695
  other v2: 5240,3042.8 5185,3045
-3V_U_HS: C52.2 C67.2 U20.8 U24.5
  other v1: 2035,2750 2035,2780
  other v2: 1760,3042.8 1820,3042.8
-3V_U_LS: C77.2 C87.2 U26.8 U28.5
  other v1: 2035,2050 2035,2080
  other v2: 1760,2342.8 1820,2342.8
-3V_V_HS: C30.2 C40.2 U14.8 U16.5
  other v1: 2035,3450 2035,3480
  other v2: 1760,3745 1815,3745
-3V_V_LS: C84.2 C88.2 U27.8 U29.5
  other v1: 4970,2050 4970,2080
  other v2: 5185,2115 5240,2117.2
-3V_W_HS: C37.2 C41.2 U15.8 U17.5
  other v1: 4970,3450 4970,3480
  other v2: 5185,3515 5240,3517.2
-3V_W_LS: C63.2 C68.2 U22.8 U25.5
  other v1: 4970,2750 4970,2780
  other v2: 5185,2815 5240,2817.2
-15V: C166.2 C167.2 C168.2 C194.1 C195.1 C196.1 C197.1 C203.1 C204.1 C205.1 C206.1 D7.1 L8.2 TP9.1 U32.7 U33.7 U34.7 | length 1226.3
  Top Layer w10: v1(5695,80) 5737.99,80 L8.2@5792.99,135 ; v1(5695,135) L8.2@5792.99,135 ; v1(5695,190) 5737.99,190 L8.2@5792.99,135 ; v1(5750,1090) 6010,1090 6090,1170 D7.1@6603.66,1170
  other v1: 5595,80 5645,105 5595,135 5645,165 5595,190 5900,195 5930,195 5970,195 6000,195 5690,1090 5720,1090 5720,1190 5750,1190 2495,1290 3885,1290 5275,1290
A14: C24.1 R65.2 U5.36 | length 304.8
  Top Layer w10: U5.36@7066.93,4131.69 7068.62,4130 7095,4130 7153.96,4071.04 7198.58,4071.04 C24.1@7237.63,4032 ; R65.2@7181.38,3964 7182.28,3964 7223.76,4005.48 7223.76,4018.14 C24.1@7237.63,4032 ; C24.1@7238.58,4032 C24.1@7237.63,4032
BLEED1: R1.1 R2.2 R5.1 R6.2 R9.1 R10.2 | length 914.5
  Top Layer w30: R9.1@3014.25,7250 3100,7250 ; R5.1@3014.25,7450 3100,7450 ; R1.1@3014.25,7650 3100,7650 ; R10.2@3185.75,7250 3100,7250 ; R6.2@3185.75,7450 3100,7450 ; R2.2@3185.75,7650 3100,7650 ; 3100,7250 3100,7450 ; 3100,7450 3100,7650
BLEED2: R2.1 R3.2 R6.1 R7.2 R10.1 R11.2 | length 914.5
  Top Layer w30: R10.1@3414.25,7250 3500,7250 ; R6.1@3414.25,7450 3500,7450 ; R2.1@3414.25,7650 3500,7650 ; R11.2@3585.75,7250 3500,7250 ; R7.2@3585.75,7450 3500,7450 ; R3.2@3585.75,7650 3500,7650 ; 3500,7250 3500,7450 ; 3500,7450 3500,7650
BLEED3: R3.1 R4.2 R7.1 R8.2 R11.1 R12.2 | length 914.5
  Top Layer w30: R11.1@3814.25,7250 3900,7250 ; R7.1@3814.25,7450 3900,7450 ; R3.1@3814.25,7650 3900,7650 ; R12.2@3985.75,7250 3900,7250 ; R8.2@3985.75,7450 3900,7450 ; R4.2@3985.75,7650 3900,7650 ; 3900,7250 3900,7450 ; 3900,7450 3900,7650
C14: C26.1 R66.2 U5.40 | length 298.9
  Top Layer w10: U5.40@7066.93,4068.7 7071.77,4063.86 7089.3,4063.86 7118.68,4034.47 7118.68,3957.79 7180.47,3896 R66.2@7181.38,3896 R66.2@7181.38,3896 C26.1@7181.42,3828
CAN_H: J4.7 R181.2 R182.2 U39.7 | length 1162.3
  Top Layer w10: v1(7915,4095) 7935,4115 7935,4455.4 7930,4460.4 v1(7930,4465)
  Bottom Layer w10: J4.7@7685.91,4965.47 7776.37,4965.47 R182.2@7780,4969.1 R181.2@7870,4969.1 7877.92,4969.1 7901.58,4945.45 7930,4917.03 v1(7930,4465) ; U39.7@7882.09,4060 7906.22,4060 7915,4068.78 v1(7915,4095)
CAN_L: J4.2 R181.1 R182.1 U39.6 | length 1102.6
  Bottom Layer w8: U39.6@7898.5,4160 7918.5,4160 7928.28,4169.78 7928.28,4173.28 7943.57,4188.57 7945.89,4190.89 7945.91,4194.17 7947.05,4354.32 7935,4366.38
  Bottom Layer w10: J4.2@7574.09,4910.94 7583.15,4920 7702.97,4920 7772.08,4850.9 R182.1@7780,4850.9 R181.1@7870,4850.9 7876.34,4850.9 7900,4827.24 7900,4401.38 7935,4366.38 ; U39.6@7882.09,4160 U39.6@7898.5,4160
CAN_RX: U5.87 U39.2 | length 1193.4
  Top Layer w10: U5.87@6933.07,3186.81 6971.51,3186.81 6986.54,3201.85 7018.15,3201.85 v1(7020.04,3199.96)
  Bottom Layer w10: v1(7020.04,3199.96) 7020.04,3255.04 7465.71,3700.71 7465.71,3802.42 7451.5,3816.64 7451.5,4030 7481.5,4060 U39.2@7517.91,4060
CAN_TX: U5.88 U39.3 | length 1331.6
  Top Layer w10: v1(6990,3165) 7025.39,3165 7036.54,3176.16 7042.5,3176.16 7053.15,3186.81 U5.88@7066.93,3186.81
  Bottom Layer w10: v1(6990,3165) 6990,3253.28 7445.71,3709 7445.71,3794.14 7431.5,3808.35 7431.5,4051.99 7474.65,4095.14 7474.65,4151.22 7483.43,4160 U39.3@7517.91,4160
COS: C22.1 R63.2 U5.34 | length 177.7
  Top Layer w10: U5.34@7066.93,4163.19 C22.1@7176.61,4163.19 ; R63.2@7181.38,4100 C22.1@7181.42,4168 C22.1@7181.42,4168
COS_N: C180.2 D10.6 J16.6 R239.1 R240.1 | length 1079.9
  Top Layer w8: 7528.27,673.3 7547.3,654.27 7587.84,654.27 7601.48,640.63 7625,640.63 7690,705.63 7690,785 7740.5,835.5 7814.5,835.5 J16.6@7860,790
  Top Layer w10: D10.6@7524.41,699.37 7524.41,685.59 7528.27,681.73 7528.27,673.3
  Bottom Layer w8: R239.1@7688,716.38 7786.38,716.38 J16.6@7860,790
  Bottom Layer w10: R240.1@7558.62,771 7636.02,771 7638.59,773.58 7644.89,773.58 7650.75,779.43 7650.75,797.62 7656.61,803.48 7707.73,803.48 7740.74,836.5 7813.5,836.5 J16.6@7860,790
COS_P: C180.1 D10.3 J16.5 R239.2 R242.1 | length 520.5
  Top Layer w10: D10.3@7575.59,620.63 7633.11,620.63 7755.98,743.5 7755.98,785.98 J16.5@7760,790
  Bottom Layer w10: R242.1@7558.62,703 7608.58,703 7622,716.42 7622,717.37 7635.86,731.24 7648.52,731.24 7690,772.72 R239.2@7690,773.62 ; R239.2@7688,773.62 7688,774.53 7696.96,783.48 7753.48,783.48 J16.5@7760,790
DC+: C114.1 C114.2 C115.1 C115.2 C116.1 C116.2 J2.1 J2.2 J2.3 J2.4 J2.5 J2.6 J2.7 J2.8 Q2.DC+_1 Q2.DC+_2 Q2.DC+_3 R1.2 R5.2 R9.2 R13.1 TP1.1 TP2.1 | length 1654.8
  Top Layer w10: 5749.61,6803.46 5749.61,7079.61 5875,7205 6325,7205 6325.12,7205.12 R13.1@6580,7205.12
  Top Layer w30: v2(2725,7500) 2730.41,7500 2751.32,7479.09 2781.89,7479.09 2785.75,7475.23 R5.2@2785.75,7450 ; R9.2@2785.75,7250 R5.2@2785.75,7450 ; R1.2@2785.75,7650 R5.2@2785.75,7450
DC+1: R13.2 R17.1 | length 79.8
  Top Layer w10: R17.1@6580,7015.12 R13.2@6580,7094.88
DC+2: R17.2 R21.1 | length 79.8
  Top Layer w10: R21.1@6580,6825.12 R17.2@6580,6904.88
DC+3: R21.2 R25.1 | length 79.8
  Top Layer w10: R25.1@6580,6635.12 R21.2@6580,6714.88
DC+4: R25.2 R29.1 | length 79.8
  Top Layer w10: R29.1@6580,6445.12 R25.2@6580,6524.88
DC+5: R29.2 R33.1 | length 79.8
  Top Layer w10: R33.1@6580,6255.12 R29.2@6580,6334.88
DC-: C114.3 C114.4 C115.3 C115.4 C116.3 C116.4 J3.1 J3.2 J3.3 J3.4 J3.5 J3.6 J3.7 J3.8 Q2.DC-1 Q2.DC-2 Q2.DC-3 R4.1 R8.1 R12.1 R152.1 TP3.1 TP4.1 | length 2171.4
  Top Layer w10: J3.4@5040,7550 5395,7550 5555,7390 v1(6105,7390)
  Top Layer w30: R12.1@4214.25,7250 R8.1@4214.25,7450 ; R4.1@4214.25,7650 R8.1@4214.25,7450 ; v2(4265,7500) 4248.11,7483.11 4218.11,7483.11 4214.25,7479.25 R8.1@4214.25,7450
  Bottom Layer w10: v1(6105,7390) 6289.88,7205.12 R152.1@6580,7205.12
DC-1: R152.2 R156.1 | length 79.8
  Bottom Layer w10: R156.1@6580,7015.12 R152.2@6580,7094.88
DC-2: R156.2 R160.1 | length 79.8
  Bottom Layer w10: R160.1@6580,6825.12 R156.2@6580,6904.88
DC-3: R160.2 R164.1 | length 79.8
  Bottom Layer w10: R164.1@6580,6635.12 R160.2@6580,6714.88
DC-4: R164.2 R168.1 | length 79.8
  Bottom Layer w10: R168.1@6580,6445.12 R164.2@6580,6524.88
DC-5: R168.2 R172.1 | length 79.8
  Bottom Layer w10: R172.1@6580,6255.12 R168.2@6580,6334.88
EXC_N: C171.2 D8.3 J16.2 R220.2 U43.9 | length 1314.3
  Top Layer w10: D8.3@7575.59,980.63 7579.4,980.63 7594.36,980.63 7614.99,960 7685.31,960 7704.55,979.24 7704.55,1018.75 7725.79,1040 7810,1040 J16.2@7860,990
  Bottom Layer w10: C171.2@7171.42,1126 R220.2@7171.38,1194 R220.2@7171.38,1194 7184.33,1206.96 7185.24,1206.96 7250.13,1271.84 7468.16,1271.84 7530,1210 7587.99,1210 7594.7,1203.29 7594.7,1169.5 7585.24,1160.04 7614.96,1160.04 7738.5,1036.5 7813.5,1036.5 J16.2@7860,990
EXC_P: C97.2 D8.6 J16.1 R135.2 U43.13 | length 932.7
  Top Layer w10: R135.2@7348.62,1022 C97.2@7348.58,1091 C97.2@7348.58,1091 7356.42,1098.84 7356.42,1186.47 7386.4,1216.46 7493.6,1216.46 7520,1190.05 7520,1190 7524.41,1185.59 7524.41,1060 7528.27,1056.14 7528.27,1034.05 7548.05,1014.27 7589.01,1014.27 7606.45,996.82 7631.81,996.82 7651.75,1016.76 7651.75,1036.75 v1(7655,1040) v1@7656.81,1038.19 ; J16.1@7751.5,998.5 J16.1@7760,990
  Bottom Layer w10: U43.13@7554.17,1053.82 7636.58,1053.82 7650.4,1040 v1(7655,1040) 7658.25,1036.75 7708.25,1036.75 7728.5,1016.5 7733.5,1016.5 J16.1@7760,990
FB_15V: C103.2 R134.2 R136.1 U35.9 | length 258.8
  Top Layer w8: R136.1@6182.24,980 6182.24,1043.62 R134.2@6183.62,1045 ; R136.1@6183.62,980 C103.2@6183.58,913 6222,913 6271.52,863.48 6271.52,860.18 6272.18,859.53 U35.9@6285.77,859.53
G1: J5.1 Q2.G1 R88.2 R92.2 R101.2 | length 412.6
  Top Layer w10: J5.1@2900.39,3800 2900.39,3589.61 2930,3560 2931.48,3560 2932.86,3558.62 3006.38,3558.62 3025,3540 3025,3520 3008.94,3503.94 Q2.G1@2996.06,3503.94 Q2.G1@2995,3505
G1H: R101.1 U20.6
G1L: R92.1 U20.7
G2: J12.1 Q2.G2 R112.2 R115.2 R123.2 | length 308.6
  Top Layer w10: Q2.G2@2870.08,2496.06 2870.08,2493.05 2900.39,2462.74 J12.1@2900.39,2200
G2H: R123.1 U26.6
G2L: R115.1 U26.7
G3: J6.1 Q2.G3 R67.2 R69.2 R77.2 | length 395.2
  Top Layer w10: Q2.G3@3374.02,3503.94 3378.94,3503.94 3420,3545 3420,3721.48 3408.62,3732.86 3408.62,3767.14 3441.48,3800 J6.1@3500.39,3800
G3H: R77.1 U14.6
G3L: R69.1 U14.7
G4: J13.1 Q2.G4 R113.2 R116.2 R124.2 | length 370.6
  Top Layer w10: J13.1@3500.39,2200 3500.39,2408.91 3580.98,2489.5 3619.42,2489.5 Q2.G4@3625.98,2496.06
G4H: R116.1 U27.6
G4L: R124.1 U27.7
G5: J7.1 Q2.G5 R68.2 R70.2 R78.2 | length 691.7
  Top Layer w10: Q2.G5@3751.97,3503.94 3706.06,3503.94 3690,3520 3690,3685 3770,3765 3995,3765 4030,3800 J7.1@4100.39,3800
G5H: R70.1 U15.6
G5L: R78.1 U15.7
G6: J14.1 Q2.G6 R89.2 R93.2 R102.2 | length 308.3
  Top Layer w10: J14.1@4100.39,2200 4100.39,2461.95 4129.92,2491.48 Q2.G6@4129.92,2496.06
G6H: R93.1 U22.6
G6L: R102.1 U22.7
GD_DIS: R81.1 U5.74 | length 651.2
  Top Layer w10: R81.1@6818.62,3480 6830,3491.38 6830,3600 6867.45,3637.45 6867.45,3642.65 6909.8,3685 6988.42,3685 6989.92,3683.5 6996.81,3683.5 7020,3660.31 7020,3427.61 7035.48,3412.13 7062.09,3412.13 U5.74@7066.93,3407.28
GD_DIS_FILT: C143.1 R81.2 R203.2 U13.1 U13.19 | length 479.6
  Top Layer w10: U13.19@6510.59,3589.41 6555.59,3589.41 6581.18,3563.82 6750.75,3563.82 v1@6766.31,3548.25 ; R81.2@6761.38,3480 6761.38,3526.78 6775,3540.4 v1(6775,3545)
  Bottom Layer w10: R203.2@6736.38,3430 C143.1@6736.42,3500 C143.1@6736.42,3500 6737.37,3500 6771.75,3534.37 6771.75,3541.75 v1(6775,3545) v1@6775,3540.4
